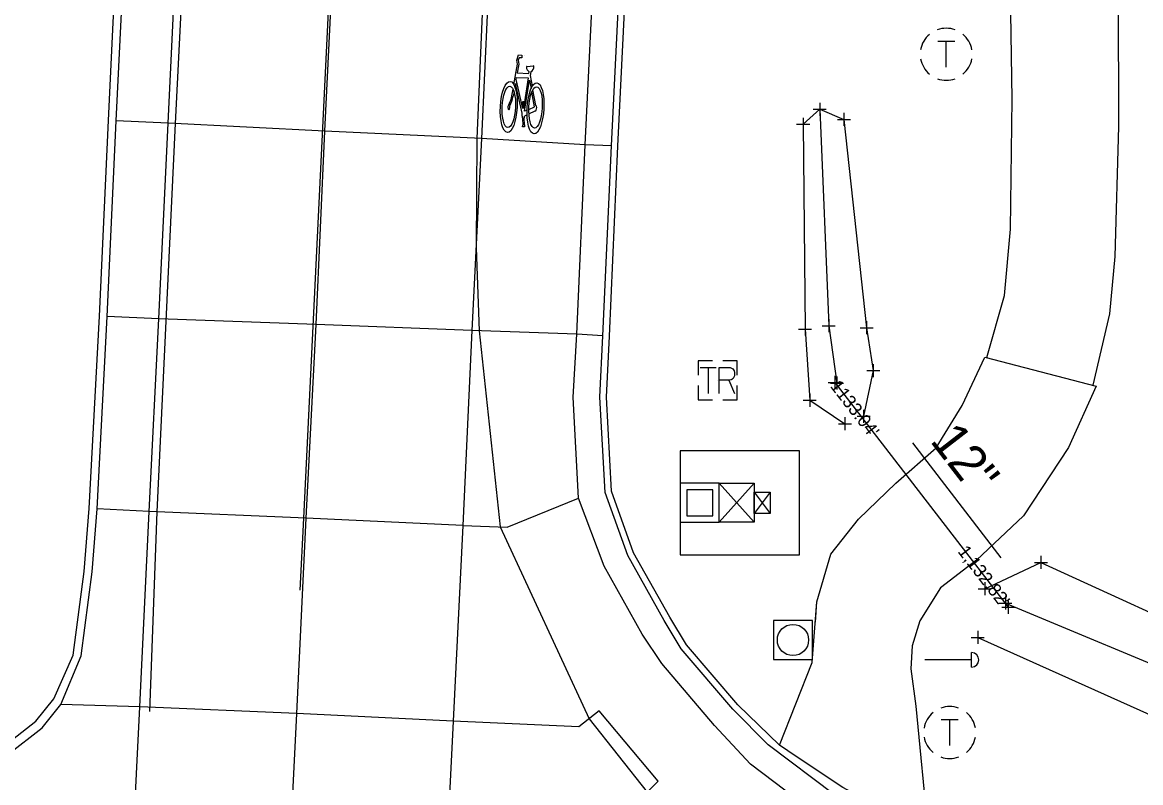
# Model space of a CAD drawing. Extents: x 207090 to 277928, y 600777 to 621109.
# Drawn here: x 261079.7 to 261165.7, y 612616.6 to 612675 of the extents above; entities that cross this region are included whole.
import ezdxf

# ---------------------------------------------------------------- set-up
doc = ezdxf.new("R2010")
doc.units = 0
for name, color, linetype in [('ATDIMS', 7, 'Continuous'), ('DR_X_Ditch', 7, 'Continuous'), ('DR_X_Storm_Sewer', 7, 'Continuous'), ('DR_X_Text', 7, 'Continuous'), ('PM_P_Edge_Line', 7, 'Continuous'), ('PM_P_Parking_Lot_Stall', 7, 'Continuous'), ('PM_P_Stop_Line', 7, 'Continuous'), ('PM_X_Cells', 7, 'Continuous'), ('PM_X_Edge_Line', 7, 'Continuous'), ('PM_X_Lane_Line', 7, 'Continuous'), ('PV_X_Curb', 7, 'Continuous'), ('PV_X_EOP', 7, 'Continuous'), ('PV_X_Joint', 7, 'Continuous'), ('PV_X_Walk', 7, 'Continuous'), ('SC_ProfileRun2', 7, 'Continuous'), ('SC_ProfileRun3', 7, 'Continuous'), ('SG_X_Detection', 7, 'Continuous'), ('SG_X_Poles', 7, 'Continuous'), ('UT_X_Water', 7, 'Continuous')]:
    doc.layers.add(name, color=color, linetype=linetype)

msp = doc.modelspace()

# ---------------------------------------------------------------- linework, layer by layer
at = {"layer": 'DR_X_Ditch'}
for points in [[(261141.01, 612668.348), (261141.697, 612651.72), (261142.322, 612647.308)], [(261155.273, 612630.412), (261170.785, 612623.936), (261181.737, 612622.038), (261224.753, 612617.764), (261254.852, 612619.275), (261313.097, 612621.284), (261371.065, 612622.869), (261453.806, 612606.883)]]:
    msp.add_lwpolyline(points, dxfattribs=at)
at = {"layer": 'DR_X_Storm_Sewer'}
msp.add_line((261142.161, 612647.367), (261155.494, 612630.086), dxfattribs=at)
at = {"layer": 'DR_X_Text'}
msp.add_line((261154.957, 612633.892), (261148.15, 612642.715), dxfattribs=at)
at = {"layer": 'PM_P_Edge_Line'}
for points in [[(261139.733, 612667.196), (261141.01, 612668.348), (261142.864, 612667.578), (261144.609, 612651.561), (261145.123, 612648.272), (261144.373, 612644.766)], [(261139.733, 612667.196), (261139.875, 612651.462), (261140.244, 612645.998), (261142.942, 612644.192)], [(261153.69, 612631.512), (261158.001, 612633.533), (261172.684, 612626.822), (261182.056, 612623.853), (261225.418, 612620.832), (261252.993, 612635.59), (261315, 612644.888), (261372.995, 612641.576)], [(261153.153, 612627.771), (261169.13, 612620.579), (261181.763, 612617.432), (261224.75, 612615.377), (261257.039, 612605.536), (261311.092, 612603.383), (261371.539, 612597.095), (261444.062, 612581.803), (261497.269, 612566.51), (261545.926, 612551.255), (261599.053, 612534.385), (261646.811, 612510.162), (261684.069, 612493.505), (261735.89, 612477.001), (261791.887, 612460.547), (261844.514, 612443.546), (261901.185, 612425.998), (261956.817, 612413.768), (262012.192, 612405.943), (262069.023, 612401.452), (262118.252, 612399.353), (262173.207, 612399.212), (262230.206, 612398.821)]]:
    msp.add_lwpolyline(points, dxfattribs=at)
at = {"layer": 'PM_P_Parking_Lot_Stall'}
msp.add_line((261133.168, 612647.518), (261133.168, 612647.518), dxfattribs=at)
for points in [[(261132.768, 612649.018), (261131.668, 612649.018), (261131.668, 612647.918)], [(261134.668, 612647.918), (261134.668, 612649.018), (261133.568, 612649.018)], [(261131.812, 612648.518), (261133.056, 612648.518)], [(261132.442, 612648.518), (261132.442, 612646.518)], [(261133.28, 612646.518), (261133.28, 612648.518), (261134.036, 612648.518), (261134.114, 612648.502), (261134.225, 612648.47), (261134.272, 612648.439), (261134.319, 612648.407), (261134.382, 612648.328), (261134.429, 612648.25), (261134.461, 612648.124), (261134.461, 612647.935), (261134.445, 612647.872), (261134.414, 612647.777), (261134.351, 612647.667), (261134.288, 612647.62), (261134.24, 612647.588), (261134.209, 612647.573), (261134.162, 612647.557), (261134.02, 612647.541), (261133.28, 612647.541)], [(261134.02, 612647.541), (261134.461, 612646.518)], [(261131.668, 612647.118), (261131.668, 612646.018), (261132.768, 612646.018)], [(261133.568, 612646.018), (261134.668, 612646.018), (261134.668, 612647.118)]]:
    msp.add_lwpolyline(points, dxfattribs=at)
at = {"layer": 'PM_P_Stop_Line'}
for p, q in [((261141.01, 612668.848), (261141.01, 612667.848)), ((261140.51, 612668.348), (261141.51, 612668.348)), ((261141.01, 612668.348), (261141.01, 612668.348)), ((261142.864, 612668.078), (261142.864, 612667.078)), ((261139.233, 612667.196), (261140.233, 612667.196)), ((261139.733, 612667.696), (261139.733, 612666.696)), ((261139.733, 612667.196), (261139.733, 612667.196)), ((261142.364, 612667.578), (261143.364, 612667.578)), ((261142.864, 612667.578), (261142.864, 612667.578)), ((261139.875, 612651.962), (261139.875, 612650.962)), ((261141.197, 612651.72), (261142.197, 612651.72)), ((261141.697, 612652.22), (261141.697, 612651.22)), ((261141.697, 612651.72), (261141.697, 612651.72)), ((261144.109, 612651.561), (261145.109, 612651.561)), ((261144.609, 612652.061), (261144.609, 612651.061)), ((261144.609, 612651.561), (261144.609, 612651.561)), ((261139.375, 612651.462), (261140.375, 612651.462)), ((261139.875, 612651.462), (261139.875, 612651.462)), ((261144.623, 612648.272), (261145.623, 612648.272)), ((261145.123, 612648.772), (261145.123, 612647.772)), ((261145.123, 612648.272), (261145.123, 612648.272)), ((261141.822, 612647.308), (261142.822, 612647.308)), ((261142.322, 612647.808), (261142.322, 612646.808)), ((261142.322, 612647.308), (261142.322, 612647.308)), ((261140.244, 612646.498), (261140.244, 612645.498)), ((261139.744, 612645.998), (261140.744, 612645.998)), ((261140.244, 612645.998), (261140.244, 612645.998)), ((261142.942, 612644.692), (261142.942, 612643.692)), ((261143.873, 612644.766), (261144.873, 612644.766)), ((261144.373, 612645.266), (261144.373, 612644.266)), ((261144.373, 612644.766), (261144.373, 612644.766)), ((261142.442, 612644.192), (261143.442, 612644.192)), ((261142.942, 612644.192), (261142.942, 612644.192)), ((261157.501, 612633.533), (261158.501, 612633.533)), ((261158.001, 612634.033), (261158.001, 612633.033)), ((261158.001, 612633.533), (261158.001, 612633.533)), ((261153.69, 612632.012), (261153.69, 612631.012)), ((261153.19, 612631.512), (261154.19, 612631.512)), ((261153.69, 612631.512), (261153.69, 612631.512)), ((261155.273, 612630.912), (261155.273, 612629.912)), ((261154.773, 612630.412), (261155.773, 612630.412)), ((261155.273, 612630.412), (261155.273, 612630.412)), ((261152.653, 612627.771), (261153.653, 612627.771)), ((261153.153, 612628.271), (261153.153, 612627.271)), ((261153.153, 612627.771), (261153.153, 612627.771))]:
    msp.add_line(p, q, dxfattribs=at)
at = {"layer": 'PM_X_Cells'}
for p, q in [((261117.893, 612672.305), (261117.829, 612672.124)), ((261118.338, 612672.507), (261118.338, 612672.507)), ((261117.873, 612671.812), (261117.761, 612671.153)), ((261117.829, 612672.124), (261117.873, 612671.812)), ((261118.494, 612671.651), (261118.999, 612671.697)), ((261117.675, 612670.649), (261117.702, 612670.806)), ((261118.176, 612668.419), (261117.675, 612670.649)), ((261117.761, 612671.153), (261118.658, 612671.107)), ((261118.604, 612670.761), (261118.233, 612668.408)), ((261118.323, 612668.202), (261118.701, 612670.599)), ((261118.658, 612671.107), (261118.679, 612671.237)), ((261118.701, 612670.599), (261118.825, 612669.943)), ((261118.799, 612671.22), (261118.758, 612670.96)), ((261118.758, 612670.96), (261118.917, 612670.12)), ((261117.512, 612669.696), (261117.454, 612669.356)), ((261117.621, 612670.335), (261117.578, 612670.082)), ((261118.136, 612668.046), (261117.621, 612670.335)), ((261119.094, 612668.528), (261118.877, 612669.673)), ((261119.198, 612668.643), (261118.967, 612669.858)), ((261118.169, 612668.923), (261118.162, 612668.784)), ((261118.162, 612668.784), (261118.195, 612668.783)), ((261118.283, 612668.917), (261118.169, 612668.923)), ((261118.195, 612668.783), (261118.176, 612668.419)), ((261118.233, 612668.408), (261118.252, 612668.78)), ((261118.252, 612668.78), (261118.276, 612668.779)), ((261118.276, 612668.779), (261118.283, 612668.917)), ((261118.135, 612667.828), (261118.136, 612668.046)), ((261118.513, 612667.918), (261118.321, 612667.817)), ((261118.511, 612668.282), (261118.323, 612668.202)), ((261118.648, 612668.34), (261119.094, 612668.528)), ((261118.656, 612667.992), (261119.137, 612668.242)), ((261118.172, 612666.993), (261118.179, 612667.138)), ((261118.314, 612667.007), (261118.172, 612666.993)), ((261118.179, 612667.138), (261118.212, 612667.141)), ((261118.212, 612667.141), (261118.198, 612667.653)), ((261118.264, 612667.666), (261118.278, 612667.147)), ((261118.278, 612667.147), (261118.322, 612667.151)), ((261118.322, 612667.151), (261118.314, 612667.007))]:
    msp.add_line(p, q, dxfattribs=at)
for points in [[(261117.499, 612670.256), (261117.765, 612671.813), (261117.72, 612672.135), (261117.86, 612672.531), (261118.113, 612672.518)], [(261118.113, 612672.518), (261118.102, 612672.294), (261117.893, 612672.305)], [(261117.702, 612670.806), (261118.604, 612670.761)], [(261117.349, 612669.374), (261117.437, 612669.891)]]:
    msp.add_lwpolyline(points, dxfattribs=at)
for centre, radius, start, end in [((261118.511, 612671.608), 0.0466, 111.12911, 179.5051), ((261118.881, 612671.601), 0.417, 178.97262, 240.92102), ((261118.558, 612671.636), 0.48, 300.03067, 4.20984), ((261119.001, 612671.658), 0.0392, 20.50857, 92.32343), ((261114.176, 612670.113), 3.257, 335.23767, 346.88251), ((261114.176, 612670.113), 3.364, 333.43857, 346.99131)]:
    msp.add_arc(centre, radius, start, end, dxfattribs=at)
for centre, major_axis, ratio in [((261117.106, 612668.531), (0.108, 1.964), 0.326796), ((261117.11, 612668.532), (0.08, 1.586), 0.323056), ((261119.16, 612668.427), (0.108, 1.964), 0.326796), ((261119.166, 612668.492), (0.08, 1.586), 0.323056)]:
    msp.add_ellipse(centre, major_axis=major_axis, ratio=ratio, dxfattribs=at)
for centre, major_axis, ratio, start_param, end_param in [((261117.116, 612668.535), (0.009, 0.217), 0.326817, 6.147003, 11.358914), ((261119.18, 612668.432), (-0.015, -0.212), 0.334676, 5.842318, 9.382693), ((261118.228, 612667.823), (0.01, 0.176), 0.529371, 1.570796, 2.917784), ((261118.228, 612667.823), (0.01, 0.176), 0.529371, 3.642407, 4.712389)]:
    msp.add_ellipse(centre, major_axis=major_axis, ratio=ratio, start_param=start_param, end_param=end_param, dxfattribs=at)
at = {"layer": 'PM_X_Edge_Line'}
for points in [[(261089.523, 612622.076), (261090.091, 612637.413), (261091.504, 612667.248), (261093.003, 612697.244), (261094.274, 612727.122), (261095.583, 612757.175), (261097.047, 612787.031), (261098.277, 612817.125), (261099.725, 612846.979)], [(261122.832, 612845.883), (261121.404, 612816.002), (261120.149, 612786.056), (261118.77, 612755.995), (261117.368, 612725.974), (261115.928, 612696.08), (261114.651, 612666.116), (261114.591, 612657.714), (261114.842, 612651.327), (261116.442, 612636.254), (261123.278, 612621.512), (261127.74, 612615.888), (261131.796, 612612.306), (261136.656, 612608.872)]]:
    msp.add_lwpolyline(points, dxfattribs=at)
at = {"layer": 'PM_X_Lane_Line'}
msp.add_lwpolyline([(261160.185, 613848.044), (261157.224, 613788.518), (261153.456, 613714.102), (261149.709, 613638.684), (261147.551, 613594.321), (261143.713, 613519.629), (261141.457, 613474.813), (261139.954, 613444.818), (261137.702, 613400.001), (261135.47, 613355.016), (261131.726, 613280.274), (261129.505, 613235.343), (261125.774, 613160.566), (261123.529, 613115.606), (261121.22, 613070.714), (261117.677, 612995.939), (261114.343, 612921.159), (261112.359, 612876.25), (261110.37, 612831.526), (261106.972, 612756.617), (261104.955, 612711.682), (261101.326, 612636.936), (261101.039, 612631.407)], dxfattribs=at)
at = {"layer": 'PV_X_Curb'}
for points in [[(261082.135, 612623.045), (261083.637, 612626.392), (261084.485, 612632.825), (261084.869, 612637.668), (261085.642, 612652.466), (261086.336, 612667.495), (261087.07, 612682.547), (261087.764, 612697.488), (261088.453, 612712.434), (261089.159, 612727.369), (261089.899, 612742.429), (261090.55, 612757.406), (261091.249, 612772.194), (261091.908, 612787.25), (261092.545, 612802.136), (261093.262, 612817.358), (261093.932, 612832.304), (261094.593, 612847.213), (261095.267, 612862.093), (261095.65, 612868.752), (261094.558, 612875.963)], [(261162.222, 612609.546), (261157.708, 612610.383), (261154.423, 612611.045), (261149.35, 612612.687), (261147.828, 612613.509), (261142.777, 612616.239), (261139.205, 612618.615), (261137.909, 612619.478), (261134.707, 612622.588), (261130.758, 612627.188), (261129.474, 612629.326), (261126.704, 612634.279), (261125.009, 612638.996), (261124.605, 612646.219), (261124.839, 612650.927), (261125.492, 612665.512), (261126.24, 612680.571)], [(261060.932, 612624.295), (261062.151, 612622.315), (261063.581, 612621.2), (261066.065, 612619.591), (261068.17, 612618.64), (261069.767, 612618.047), (261071.27, 612617.641), (261073.51, 612617.633), (261075.626, 612618.16), (261078.25, 612619.364), (261080.751, 612621.326), (261082.135, 612623.045)]]:
    msp.add_lwpolyline(points, dxfattribs=at)
at = {"layer": 'PV_X_EOP'}
for points in [[(261082.678, 612622.603), (261084.236, 612626.362), (261085.084, 612632.796), (261085.468, 612637.638), (261086.242, 612652.437), (261086.935, 612667.467), (261087.67, 612682.518), (261088.364, 612697.46), (261089.052, 612712.406), (261089.758, 612727.34), (261090.498, 612742.401), (261091.149, 612757.379), (261091.848, 612772.166), (261092.508, 612787.224), (261093.144, 612802.108), (261093.861, 612817.33), (261094.532, 612832.277), (261095.193, 612847.186), (261095.866, 612862.067), (261096.25, 612868.728), (261095.146, 612876.083)], [(261162.133, 612609.054), (261157.607, 612609.893), (261154.292, 612610.563), (261150.351, 612611.748), (261146.409, 612613.436), (261142.144, 612615.659), (261137.035, 612619.515), (261134.334, 612622.255), (261130.36, 612626.886), (261129.048, 612629.064), (261126.25, 612634.069), (261124.52, 612638.893), (261124.105, 612646.221), (261124.34, 612650.954), (261124.993, 612665.536), (261125.741, 612680.596)], [(261060.334, 612623.925), (261061.62, 612621.839), (261063.173, 612620.627), (261065.727, 612618.973), (261067.902, 612617.99), (261069.551, 612617.377), (261071.175, 612616.939), (261073.593, 612616.93), (261075.857, 612617.494), (261078.616, 612618.76), (261081.244, 612620.823), (261082.678, 612622.603)]]:
    msp.add_lwpolyline(points, dxfattribs=at)
at = {"layer": 'PV_X_Joint'}
for points in [[(261084.563, 612537.187), (261085.223, 612551.045), (261085.9, 612565.025), (261086.623, 612580.129), (261087.24, 612592.654), (261087.999, 612607.512), (261088.74, 612622.44), (261089.48, 612637.439), (261090.222, 612652.244), (261090.927, 612667.278), (261091.65, 612682.328), (261092.356, 612697.274), (261093.044, 612712.219), (261093.75, 612727.147), (261094.49, 612742.216), (261095.143, 612757.196), (261095.85, 612771.984), (261096.502, 612787.052), (261097.139, 612801.927), (261097.87, 612817.146), (261098.526, 612832.101), (261099.187, 612847.006)], [(261096.656, 612536.623), (261097.322, 612550.588), (261097.961, 612564.477), (261098.667, 612579.459), (261099.382, 612592.176), (261100.087, 612607.019), (261100.83, 612621.92), (261101.545, 612636.927), (261102.299, 612651.813), (261102.969, 612666.67), (261103.725, 612681.791), (261104.442, 612696.713), (261105.142, 612711.673), (261105.84, 612726.564), (261106.549, 612741.587), (261107.265, 612756.603), (261107.931, 612771.448), (261108.603, 612786.578), (261109.282, 612801.366), (261109.96, 612816.526), (261110.6, 612831.515), (261111.269, 612846.392)], [(261123.295, 612845.862), (261122.606, 612830.954), (261121.896, 612815.979), (261121.264, 612800.893), (261120.588, 612786.036), (261119.895, 612770.923), (261119.222, 612755.971), (261118.516, 612740.93), (261117.798, 612725.952), (261117.149, 612711.101), (261116.432, 612696.052), (261115.707, 612681.201), (261115.013, 612666.099), (261114.27, 612651.347), (261113.57, 612636.358), (261112.838, 612621.333), (261112.099, 612606.453), (261111.389, 612591.636), (261110.733, 612578.912), (261110.029, 612563.934), (261109.316, 612550.044), (261108.642, 612536.117)], [(261122.05, 612646.227), (261122.346, 612651.058), (261122.984, 612665.63), (261123.733, 612680.697), (261124.489, 612695.628), (261124.59, 612710.811), (261124.685, 612725.629), (261124.813, 612740.616), (261125.001, 612755.723), (261124.987, 612770.732), (261125.025, 612785.921), (261125.351, 612800.665), (261125.883, 612815.788), (261126.511, 612830.752), (261127.196, 612845.723)], [(261124.993, 612665.536), (261122.984, 612665.63), (261115.013, 612666.099), (261102.969, 612666.67), (261090.927, 612667.278), (261086.935, 612667.467)], [(261124.34, 612650.954), (261122.346, 612651.058), (261114.27, 612651.347), (261102.299, 612651.813), (261090.222, 612652.244), (261086.242, 612652.437)], [(261161.755, 612606.978), (261157.178, 612607.81), (261153.758, 612608.599), (261149.664, 612609.885), (261145.56, 612611.63), (261141.068, 612613.955), (261135.694, 612618.027), (261132.917, 612620.991), (261128.873, 612625.76), (261127.348, 612628.018), (261124.439, 612633.23), (261122.476, 612638.464), (261122.05, 612646.227)], [(261113.57, 612636.358), (261116.986, 612636.234), (261122.476, 612638.464)], [(261113.57, 612636.358), (261101.545, 612636.927), (261089.48, 612637.439), (261085.468, 612637.638)], [(261122.493, 612620.904), (261112.838, 612621.333), (261100.83, 612621.92), (261088.74, 612622.44), (261082.678, 612622.603)], [(261112.583, 612535.945), (261113.257, 612549.845), (261114.114, 612564.244), (261119.686, 612564.89), (261125.029, 612565.014), (261125.586, 612578.465), (261126.101, 612590.883), (261126.712, 612605.352), (261127.19, 612615.346), (261128.585, 612616.719), (261124.059, 612622.117), (261122.493, 612620.904)]]:
    msp.add_lwpolyline(points, dxfattribs=at)
at = {"layer": 'PV_X_Walk'}
for points in [[(261153.853, 612649.274), (261155.198, 612654.043), (261155.669, 612659.127), (261155.8, 612669.123), (261155.654, 612679.119), (261155.178, 612689.108), (261154.586, 612699.09), (261153.796, 612709.059), (261153.577, 612719.049), (261153.633, 612729.049), (261153.629, 612739.049), (261153.624, 612749.05), (261153.524, 612759.05), (261153.395, 612769.049), (261153.266, 612779.049), (261153.183, 612789.049), (261153.141, 612799.049), (261153.099, 612809.049), (261153.022, 612819.049), (261152.918, 612829.049)], [(261162.013, 612647.143), (261163.302, 612652.622), (261163.711, 612657.041), (261163.987, 612667.031), (261163.963, 612677.029), (261163.487, 612687.018), (261162.977, 612697.005), (261162.187, 612706.974), (261161.762, 612716.957), (261161.835, 612726.957), (261161.83, 612736.957), (261161.825, 612746.957), (261161.752, 612756.957), (261161.623, 612766.957), (261161.494, 612776.957), (261161.392, 612786.956), (261161.35, 612796.957), (261161.309, 612806.957), (261161.244, 612816.957), (261161.121, 612828.791)], [(261140.668, 612628.946), (261140.786, 612630.498), (261141.863, 612634.155), (261143.983, 612636.844), (261146.862, 612639.625), (261149.956, 612642.331), (261151.955, 612645.587), (261153.705, 612649.313), (261162.255, 612647.08), (261160.124, 612642.354), (261156.679, 612637.106), (261153.045, 612633.695), (261150.29, 612631.589), (261148.698, 612629.032), (261148.112, 612627.118), (261148.011, 612625.357), (261148.386, 612622.494), (261149.35, 612612.687), (261147.828, 612613.509), (261142.777, 612616.239), (261139.205, 612618.615)], [(261139.205, 612618.615), (261137.909, 612619.478), (261140.432, 612625.841), (261140.786, 612630.498)]]:
    msp.add_lwpolyline(points, dxfattribs=at)
at = {"layer": 'SC_ProfileRun2'}
for p, q in [((261141.661, 612647.367), (261142.661, 612647.367)), ((261142.161, 612647.867), (261142.161, 612646.867)), ((261142.161, 612647.367), (261142.161, 612647.367)), ((261154.994, 612630.086), (261155.994, 612630.086)), ((261155.494, 612630.586), (261155.494, 612629.586)), ((261155.494, 612630.086), (261155.494, 612630.086))]:
    msp.add_line(p, q, dxfattribs=at)
at = {"layer": 'SC_ProfileRun3'}
for p, q in [((261150.08, 612673.58), (261151.38, 612673.58)), ((261150.73, 612671.58), (261150.73, 612673.58)), ((261150.73, 612672.58), (261150.73, 612672.58)), ((261150.35, 612621.459), (261151.65, 612621.459)), ((261151, 612619.459), (261151, 612621.459)), ((261151, 612620.459), (261151, 612620.459))]:
    msp.add_line(p, q, dxfattribs=at)
for centre, start, end in [((261150.729, 612672.579), 130.0806, 170.07213), ((261150.729, 612672.579), 70.05767, 110.10608), ((261150.729, 612672.579), 10.01689, 50.03919), ((261150.729, 612672.579), 190.01689, 230.03919), ((261150.729, 612672.579), 310.01144, 350.02638), ((261150.729, 612672.579), 250.05767, 290.04731), ((261151, 612620.459), 70.05767, 110.10608), ((261151, 612620.459), 130.0806, 170.07213), ((261151, 612620.459), 10.01689, 50.03919), ((261151, 612620.459), 190.01689, 230.03919), ((261151, 612620.459), 310.01144, 350.02638), ((261151, 612620.459), 250.05767, 290.04731)]:
    msp.add_arc(centre, 2, start, end, dxfattribs=at)
at = {"layer": 'SG_X_Detection'}
for p, q in [((261152.673, 612625.484), (261152.673, 612626.604)), ((261152.673, 612626.044), (261149.073, 612626.044))]:
    msp.add_line(p, q, dxfattribs=at)
msp.add_arc((261152.673, 612626.044), 0.56, 270.00019, 89.99981, dxfattribs=at)
at = {"layer": 'SG_X_Poles'}
msp.add_lwpolyline([(261137.448, 612626.069), (261140.448, 612626.069), (261140.448, 612629.069), (261137.448, 612629.069)], close=True, dxfattribs=at)
msp.add_circle((261138.948, 612627.569), 1.2, dxfattribs=at)
at = {"layer": 'UT_X_Water'}
for p, q in [((261133.289, 612639.611), (261135.954, 612636.611)), ((261135.954, 612639.611), (261133.289, 612636.611)), ((261135.954, 612638.92), (261137.2, 612637.302)), ((261137.2, 612638.92), (261135.954, 612637.302))]:
    msp.add_line(p, q, dxfattribs=at)
for points in [[(261130.289, 612642.109), (261130.289, 612634.112), (261139.45, 612634.112), (261139.45, 612642.109)], [(261130.289, 612639.611), (261130.289, 612636.611), (261133.289, 612636.611), (261133.289, 612639.611)], [(261133.289, 612639.611), (261135.954, 612639.611), (261135.954, 612636.611), (261133.289, 612636.611)], [(261130.79, 612639.11), (261130.79, 612637.111), (261132.789, 612637.111), (261132.789, 612639.11)], [(261135.954, 612638.92), (261137.2, 612638.92), (261137.2, 612637.302), (261135.954, 612637.302)]]:
    msp.add_lwpolyline(points, close=True, dxfattribs=at)

# ---------------------------------------------------------------- texts
at = {"layer": 'ATDIMS'}
for s, p in [("1133.04'", (261141.765, 612647.061)), ("1,132.82'", (261151.567, 612634.358))]:
    msp.add_text(s, height=1, rotation=307.65341, dxfattribs=at).set_placement(p)
at = {"layer": 'DR_X_Text'}
msp.add_text('12" ', height=2.8, rotation=307.65341, dxfattribs=at).set_placement((261149.424, 612642.867))

doc.saveas('drawing.dxf')
